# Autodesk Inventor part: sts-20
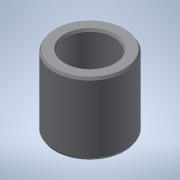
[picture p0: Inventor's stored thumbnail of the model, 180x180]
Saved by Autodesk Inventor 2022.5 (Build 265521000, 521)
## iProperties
Created: 2016-12
Part Number: sts-20
Material: 一般
Document SubType Name: Modeling
Designer: imaocorp
Density: 1 g/cm^3
Appearance: 既定
Author: imaocorp
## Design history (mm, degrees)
node "sts-20.x_t1"
node "sts-20"
node "Base1"
